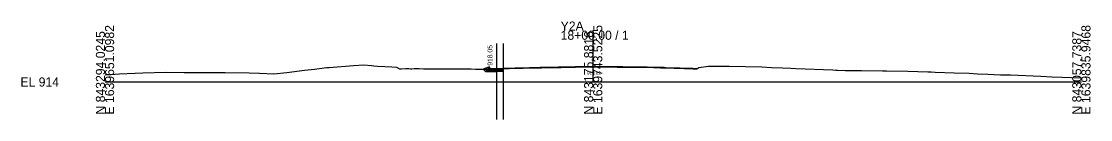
# Model space of a CAD drawing. Extents: x -26 to 303, y -10 to 10517.
# Drawn here: x -25.7 to 302.8, y 7488.4 to 7518.6 of the extents above; entities that cross this region are included whole.
import ezdxf

# ---------------------------------------------------------------- set-up
doc = ezdxf.new("R2010")
doc.units = 0
for name, color, linetype in [('Exist Cross Section Cell', 7, 'Continuous'), ('Exist XS Center Line Elevation Label', 7, 'Continuous'), ('Exist XS Ground Line', 7, 'Continuous'), ('Prop CMT Conc Surface', 7, 'Continuous'), ('Prop CMT Concrete Structures', 7, 'Continuous'), ('Prop CMT Pvmt Course 1', 7, 'Continuous'), ('Prop CMT Pvmt Course 1 CG', 7, 'Continuous'), ('Prop CMT Pvmt Course 2', 7, 'Continuous'), ('Prop CMT Pvmt Surface Overlay', 7, 'Continuous'), ('Prop CMT Slope Grass', 7, 'Continuous'), ('Prop CMT Subgrade Earthwork', 7, 'Continuous'), ('Prop XS Hydro Elevations', 7, 'Continuous'), ('Scratch_Level_0', 7, 'Continuous'), ('Scratch_Level_2', 7, 'Continuous')]:
    doc.layers.add(name, color=color, linetype=linetype)

msp = doc.modelspace()

# ---------------------------------------------------------------- linework, layer by layer
at = {"layer": 'Exist Cross Section Cell'}
for p, q in [((150, 7500), (150, 7515.76)), ((0, 7500), (150, 7500)), ((150, 7500), (300, 7500))]:
    msp.add_line(p, q, dxfattribs=at)
at = {"layer": 'Exist XS Ground Line'}
msp.add_lwpolyline([(0, 7502.19), (4.48, 7502.52), (11.62, 7502.85), (18.73, 7503.03), (24.29, 7502.88), (26.72, 7502.94), (28.45, 7502.9), (36.93, 7502.95), (44.28, 7502.84), (47.52, 7502.75), (51.86, 7502.51), (55.92, 7502.94), (61.29, 7503.6), (64.37, 7503.95), (67.37, 7504.33), (68.18, 7504.43), (68.86, 7504.49), (76.36, 7505.03), (79.53, 7505.25), (81.89, 7505.01), (82.59, 7504.97), (83.74, 7504.9), (86, 7504.75), (88.11, 7504.6), (89.58, 7504.52), (90.53, 7504.08), (90.95, 7504.07), (92.4, 7504.14), (92.71, 7504.14), (93.37, 7504.13), (93.87, 7504.07), (94.26, 7504.07), (94.96, 7504.1), (95.58, 7504.1), (96.54, 7504.09), (97.89, 7504.08), (98.75, 7504.07), (100.03, 7504.06), (101.92, 7504.04), (103.6, 7504.03), (105.38, 7504.01), (105.74, 7504.01), (107.16, 7504.02), (108.27, 7504.01), (108.94, 7504.01), (109.8, 7504), (110.72, 7504), (111.44, 7504), (112.5, 7503.99), (113.85, 7503.97), (114.28, 7503.97), (114.62, 7503.97), (116.06, 7503.96), (117.91, 7503.94), (120.97, 7504.05), (121.41, 7504.06), (121.97, 7504.07), (123.19, 7504.1), (124.14, 7504.13), (126.02, 7504.19), (127.31, 7504.23), (128.53, 7504.25), (130.49, 7504.31), (132.09, 7504.34), (133.66, 7504.38), (134.14, 7504.39), (135.65, 7504.41), (136.84, 7504.44), (137.43, 7504.45), (138.2, 7504.46), (139.21, 7504.48), (140.01, 7504.49), (141, 7504.52), (142.25, 7504.53), (142.78, 7504.54), (143.18, 7504.55), (144.56, 7504.58), (146.36, 7504.61), (148.12, 7504.64), (149.53, 7504.63), (150, 7504.62), (150.37, 7504.62), (151.68, 7504.62), (152.71, 7504.62), (153.46, 7504.62), (154.43, 7504.61), (155.24, 7504.6), (155.88, 7504.6), (157.41, 7504.59), (158.48, 7504.59), (159.05, 7504.59), (160.19, 7504.58), (160.67, 7504.57), (161.65, 7504.58), (162.23, 7504.58), (162.54, 7504.57), (165.4, 7504.52), (165.93, 7504.52), (166.6, 7504.5), (168.58, 7504.44), (169.48, 7504.42), (170.66, 7504.39), (171.13, 7504.38), (171.68, 7504.37), (171.99, 7504.37), (172.34, 7504.35), (174.93, 7504.26), (176.61, 7504.22), (178.1, 7504.16), (178.58, 7504.14), (180.01, 7504.09), (180.57, 7504.06), (181.89, 7504), (182.41, 7504.47), (185.42, 7504.81), (186.01, 7504.82), (189.71, 7504.85), (191.77, 7504.81), (201.83, 7504.64), (204.83, 7504.46), (208.21, 7504.32), (210.71, 7504.22), (212.22, 7504.14), (223.63, 7503.68), (224.59, 7503.62), (225.11, 7503.61), (227.45, 7503.53), (232.45, 7503.56), (238.85, 7503.45), (240.14, 7503.45), (246.7, 7503.3), (252.84, 7503.14), (253.82, 7503.08), (255.08, 7503.05), (260.95, 7502.82), (265.54, 7502.71), (268.07, 7502.54), (271.31, 7502.39), (275.19, 7502.18), (278.24, 7502.16), (287.54, 7501.76), (290.93, 7501.59), (300, 7501.23)], dxfattribs=at)
at = {"layer": 'Prop CMT Conc Surface'}
msp.add_lwpolyline([(118.29, 7504.05), (118.29, 7504.55), (117.79, 7504.55)], dxfattribs=at)
at = {"layer": 'Prop CMT Concrete Structures'}
for points in [[(120.29, 7504.17), (118.29, 7504.05), (118.29, 7504.55), (117.79, 7504.55)], [(117.79, 7504.55), (117.79, 7503.53), (120.29, 7503.58)]]:
    msp.add_lwpolyline(points, dxfattribs=at)
at = {"layer": 'Prop CMT Pvmt Course 1'}
for p, q in [((120.29, 7504.17), (122.29, 7504.2)), ((120.29, 7504.17), (120.29, 7503.92)), ((120.29, 7503.92), (122.29, 7503.95)), ((122.29, 7504.2), (122.29, 7503.95))]:
    msp.add_line(p, q, dxfattribs=at)
at = {"layer": 'Prop CMT Pvmt Course 1 CG'}
for p, q in [((120.29, 7503.59), (120.29, 7503.25)), ((120.29, 7503.25), (122.29, 7503.29)), ((122.29, 7503.62), (122.29, 7503.29))]:
    msp.add_line(p, q, dxfattribs=at)
for points in [[(120.29, 7503.58), (117.29, 7503.52), (116.95, 7503.19)], [(116.99, 7503.19), (120.29, 7503.25)]]:
    msp.add_lwpolyline(points, dxfattribs=at)
at = {"layer": 'Prop CMT Pvmt Course 2'}
for p, q in [((120.29, 7503.59), (120.29, 7503.92)), ((122.29, 7503.62), (122.29, 7503.95)), ((120.29, 7503.59), (122.29, 7503.62))]:
    msp.add_line(p, q, dxfattribs=at)
at = {"layer": 'Prop CMT Pvmt Surface Overlay'}
msp.add_lwpolyline([(122.29, 7504.2), (123.18, 7504.22), (124.14, 7504.25), (126.02, 7504.32), (127.31, 7504.35), (128.53, 7504.38), (130.48, 7504.44), (132.09, 7504.47), (133.66, 7504.5), (134.14, 7504.51), (135.65, 7504.54), (136.83, 7504.56), (137.43, 7504.57), (138.2, 7504.58), (139.21, 7504.6), (140.01, 7504.62), (140.99, 7504.64), (142.25, 7504.66), (142.77, 7504.67), (143.18, 7504.67), (144.55, 7504.71), (146.36, 7504.74), (148.12, 7504.76), (149.53, 7504.75), (150, 7504.75), (150.37, 7504.75), (151.68, 7504.75), (152.71, 7504.74), (153.46, 7504.74), (154.43, 7504.73), (155.24, 7504.73), (155.88, 7504.72), (157.41, 7504.72), (158.48, 7504.72), (159.06, 7504.72), (160.19, 7504.7), (160.67, 7504.7), (161.65, 7504.7), (162.23, 7504.7), (162.54, 7504.7), (165.4, 7504.65), (165.93, 7504.64), (166.6, 7504.62), (168.58, 7504.57), (169.48, 7504.55), (170.66, 7504.52), (171.14, 7504.51), (171.68, 7504.5), (172, 7504.49), (172.35, 7504.48), (174.93, 7504.38), (176.62, 7504.34), (178.1, 7504.28), (178.59, 7504.26), (180.01, 7504.21), (180.57, 7504.19), (182.03, 7504.12)], dxfattribs=at)
at = {"layer": 'Prop CMT Slope Grass'}
msp.add_lwpolyline([(117.79, 7504.55), (116.18, 7503.96)], dxfattribs=at)
at = {"layer": 'Prop CMT Subgrade Earthwork'}
msp.add_lwpolyline([(120.29, 7503.25), (116.95, 7503.19), (116.18, 7503.96)], dxfattribs=at)
at = {"layer": 'Scratch_Level_0'}
for p, q in [((120.29, 7511.79), (120.29, 7488.44)), ((122.29, 7511.79), (122.29, 7488.44))]:
    msp.add_line(p, q, dxfattribs=at)
at = {"layer": 'Scratch_Level_2'}
msp.add_line((122.29, 7504.08), (121.97, 7504.07), dxfattribs=at)
for points in [[(116.18, 7503.96), (116.95, 7503.19), (120.29, 7503.25), (122.29, 7503.29), (122.29, 7504.08)], [(116.18, 7503.96), (116.95, 7503.19), (120.29, 7503.25), (122.29, 7503.29), (122.29, 7504.08)], [(121.97, 7504.07), (121.41, 7504.06), (120.97, 7504.05), (117.91, 7503.94), (116.18, 7503.96)]]:
    msp.add_lwpolyline(points, dxfattribs=at)

# ---------------------------------------------------------------- texts
at = {"layer": 'Exist Cross Section Cell'}
for s, p in [('E 1639651.0982', (2.8, 7490)), ('E 1639743.5225', (152.8, 7490)), ('E 1639835.9468', (302.8, 7490)), ('N 843294.0245', (0, 7490)), ('N 843175.8816', (150, 7490)), ('N 843057.7387', (300, 7490))]:
    msp.add_text(s, height=2.8, rotation=90, dxfattribs=at).set_placement(p)
for s, p in [('Y2A', (140, 7515.76)), ('18+00.00 / 1', (140, 7512.96)), ('EL 914', (-26, 7498.6))]:
    msp.add_text(s, height=2.8, dxfattribs=at).set_placement(p)
at = {"layer": 'Exist XS Center Line Elevation Label'}
msp.add_text('918.62', height=1, dxfattribs=at).set_placement((148.11, 7502.22))
at = {"layer": 'Prop XS Hydro Elevations'}
msp.add_text('918.05', height=1.5, rotation=90, dxfattribs=at).set_placement((119.04, 7505))

doc.saveas('drawing.dxf')
